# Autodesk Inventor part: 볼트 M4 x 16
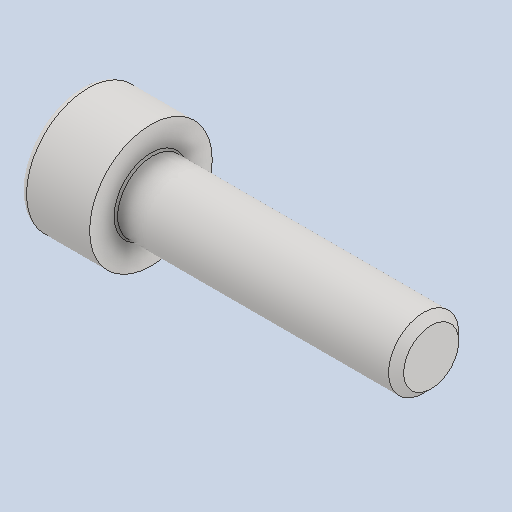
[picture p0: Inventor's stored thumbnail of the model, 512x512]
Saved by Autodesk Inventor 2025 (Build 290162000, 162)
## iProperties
Created: 2024-07
Part Number: 볼트 M4 x 16
Material: 스테인리스강
Description: 6각 소켓 머리 캡 나사
Document SubType Name: Modeling
Designer: samsung
Density: 8.08 g/cm^3
Appearance: 기본값
Author: jhkim
Sending System: Autodesk Inventor 2025
Preprocessor: ST-DEVELOPER v20
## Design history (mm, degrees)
feature "Solid1"
node "솔리드1"
